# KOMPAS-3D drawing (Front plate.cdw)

Views: View 1, Front, View 3, Isometric YZX
Referenced files in C:\Work\01 К О М П А С\Модели примеры\2009_04_For_Poland_AXAPACK\My sample\: Front_plate.a3d, Front_plate.m3d, rail3.m3d
Referenced files in D:\Documents and Settings\kashirsky\Рабочий стол\: GRAPHIC_DE.LYT
Referenced files: Front plate.cdw
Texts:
  Front plate
  Drawing Annotation
  Dimension Texts
  Surface Finish
  Leader #1
  Leader #2
  Leader #3
  Shape Deviations and Datum
  Table Header
  Table Cell
  Cut/Section Line
  Direction Arrow
  Modification Symbol
  Brace
  Node point number
  Mark of coordination axis
  VRCB
  Leader Text
  Node point designation
  Mark/Reference designation with leader
  Mark/reference designation on line
  Mark/Reference designation without leader
  System Layer
  System View
  Projection View 2
  Specifications
  Unspecified Surface Finish
  BOM table name
  Rail
Dimensions and other numbers on the sheet: 7; 2880; 2000; 1:1; 1; 766,16; 0; 2; 3; 4; 5; 6; 8; 9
